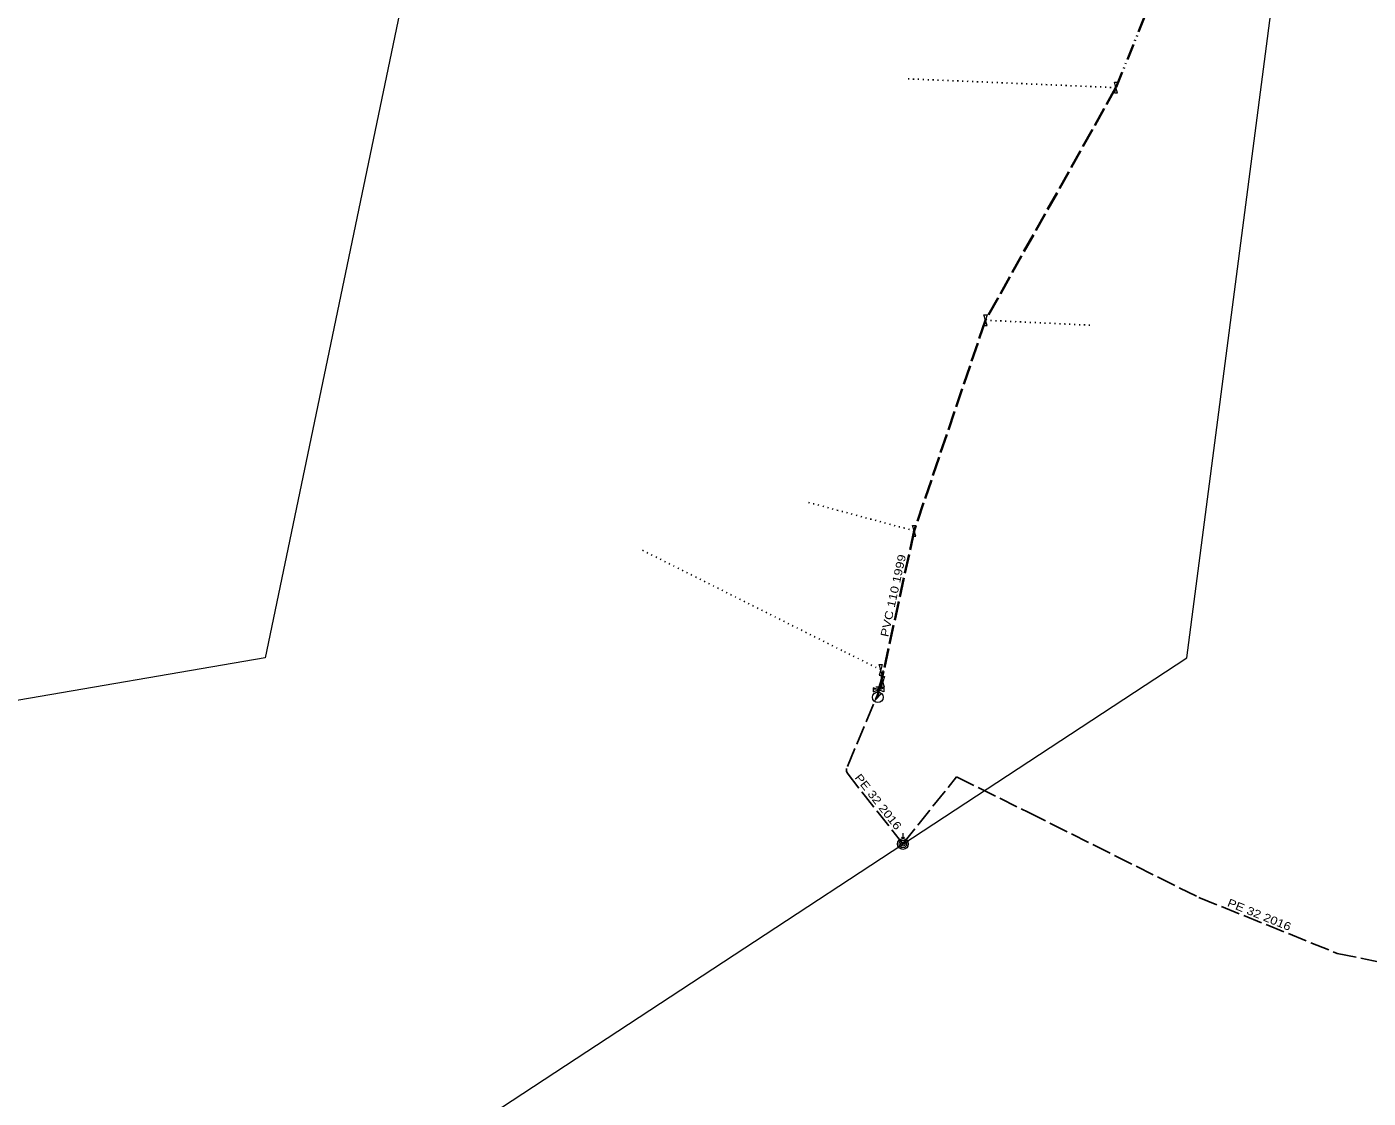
# Model space of a CAD drawing. Extents: x -582626 to -580899, y -1097611 to -1096610.
# Drawn here: x -581490.3 to -581365.1, y -1097012.4 to -1096912.4 of the extents above; entities that cross this region are included whole.
import ezdxf
from ezdxf.enums import TextEntityAlignment as Align

# ---------------------------------------------------------------- set-up
doc = ezdxf.new("R2010")
doc.units = 0
doc.header["$LTSCALE"] = 0.3
for name, pattern in [('DASH_DOUBLE_DOT', [9.2, 5, -1.2, 0.3, -1.2, 0.3, -1.2]), ('DOTTED', [1.5, 0.3, -1.2]), ('LONG_DASHED', [7.5, 6, -1.5])]:
    doc.linetypes.add(name, pattern=pattern)
for name, color, linetype, lineweight in [('1', 7, 'Continuous', 13), ('10', 7, 'Continuous', 13), ('35', 7, 'LONG_DASHED', 35), ('36', 7, 'DASH_DOUBLE_DOT', 35), ('50', 7, 'LONG_DASHED', 25), ('51', 7, 'DOTTED', 25)]:
    doc.layers.add(name, color=color, linetype=linetype, lineweight=lineweight)
doc.layers.add('16', color=7, linetype='Continuous')
doc.layers.add('19', color=7, linetype='Continuous')

msp = doc.modelspace()

# ---------------------------------------------------------------- linework, layer by layer
at = {"layer": '1'}
msp.add_lwpolyline([(-582625.57, -1097394.66), (-582612.34, -1097467.421), (-582321.299, -1097262.369), (-581897.965, -1097202.837), (-581719.372, -1097182.994), (-581593.695, -1097110.233), (-581382.028, -1096971.327), (-581362.184, -1096819.192), (-581322.497, -1096739.817), (-581210.049, -1096733.202), (-581097.601, -1096686.9), (-580905.778, -1096719.973), (-580899.163, -1096627.369), (-581084.372, -1096614.14), (-581216.663, -1096680.285), (-581368.799, -1096686.9), (-581434.945, -1096812.577), (-581468.018, -1096971.327), (-581659.84, -1097004.4), (-581831.82, -1097110.233), (-582314.684, -1097169.765), (-582519.736, -1097295.442), (-582625.57, -1097394.66)], close=True, dxfattribs=at)
at = {"layer": '10'}
for p, q in [((-581411.204, -1096975.373), (-581410.497, -1096974.666)), ((-581411.2, -1096974.219), (-581410.5, -1096974.219)), ((-581410.793, -1096974.069), (-581411.043, -1096974.069)), ((-581410.85, -1096974.519), (-581410.85, -1096974.219)), ((-581408.516, -1096988.209), (-581408.657, -1096988.068))]:
    msp.add_line(p, q, dxfattribs=at)
for points in [[(-581388.633, -1096918.118), (-581388.783, -1096917.618), (-581388.483, -1096917.618), (-581388.633, -1096918.118), (-581388.783, -1096918.618), (-581388.483, -1096918.618)], [(-581400.808, -1096939.828), (-581400.958, -1096939.328), (-581400.658, -1096939.328), (-581400.808, -1096939.828), (-581400.958, -1096940.328), (-581400.658, -1096940.328)], [(-581407.46, -1096959.484), (-581407.61, -1096958.984), (-581407.31, -1096958.984), (-581407.46, -1096959.484), (-581407.61, -1096959.984), (-581407.31, -1096959.984)], [(-581410.585, -1096972.45), (-581410.735, -1096971.95), (-581410.435, -1096971.95), (-581410.585, -1096972.45), (-581410.735, -1096972.95), (-581410.435, -1096972.95)], [(-581410.392, -1096973.578), (-581410.542, -1096973.078), (-581410.242, -1096973.078), (-581410.392, -1096973.578), (-581410.542, -1096974.078), (-581410.242, -1096974.078)]]:
    msp.add_lwpolyline(points, close=True, dxfattribs=at)
for points in [[(-581410.793, -1096974.319), (-581410.293, -1096974.132), (-581410.293, -1096974.506), (-581410.793, -1096974.319), (-581411.293, -1096974.132), (-581411.293, -1096974.506), (-581410.793, -1096974.319), (-581410.793, -1096974.069), (-581410.543, -1096974.069)], [(-581408.516, -1096987.709), (-581408.516, -1096988.209), (-581408.375, -1096988.068)]]:
    msp.add_lwpolyline(points, dxfattribs=at)
for centre, radius in [((-581410.8498, -1096975.0187), 0.5), ((-581408.5133, -1096988.7115), 0.5), ((-581408.5133, -1096988.7115), 0.35), ((-581408.5133, -1096988.7115), 0.2)]:
    msp.add_circle(centre, radius, dxfattribs=at)
at = {"layer": '35'}
msp.add_lwpolyline([(-581388.633, -1096918.118), (-581400.808, -1096939.828), (-581407.46, -1096959.484), (-581410.318, -1096972.582), (-581410.528, -1096973.542), (-581410.793, -1096974.319), (-581410.85, -1096975.019)], dxfattribs=at)
at = {"layer": '36'}
msp.add_lwpolyline([(-581370.994, -1096843.984), (-581373.727, -1096866.006), (-581377.691, -1096885.792), (-581384.916, -1096908.945), (-581388.633, -1096918.118)], dxfattribs=at)
at = {"layer": '50'}
msp.add_lwpolyline([(-581410.392, -1096973.578), (-581413.767, -1096981.681), (-581413.782, -1096981.904), (-581413.73, -1096982.081), (-581408.514, -1096988.711), (-581403.522, -1096982.454), (-581396.825, -1096985.755), (-581380.89, -1096993.711), (-581367.988, -1096998.918), (-581338.24, -1097005.156), (-581327.828, -1097004.957), (-581321.866, -1097006.642), (-581321.47, -1097007.123), (-581319.049, -1097010.467)], dxfattribs=at)
at = {"layer": '51'}
for p, q in [((-581388.633, -1096918.118), (-581408.301, -1096917.289)), ((-581400.808, -1096939.828), (-581391.052, -1096940.295)), ((-581407.46, -1096959.484), (-581417.4, -1096956.813))]:
    msp.add_line(p, q, dxfattribs=at)
at = {"layer": '51', "linetype": 'DASH_DOUBLE_DOT'}
msp.add_line((-581410.392, -1096973.578), (-581410.528, -1096973.542), dxfattribs=at)
at = {"layer": '51'}
msp.add_lwpolyline([(-581410.318, -1096972.582), (-581410.585, -1096972.45), (-581414.224, -1096970.643), (-581432.906, -1096961.254)], dxfattribs=at)

# ---------------------------------------------------------------- texts
at = {"layer": '16', "width": 1.2}
msp.add_text('PVC 110 1999', height=0.75, rotation=77.691, dxfattribs=at).set_placement((-581409.0525, -1096965.6104), align=Align.CENTER)
at = {"layer": '19', "width": 1.2}
for rotation, p in [(308.193, (-581411.1122, -1096985.0031)), (338.022, (-581375.3983, -1096995.6578))]:
    msp.add_text('PE 32 2016', height=0.75, rotation=rotation, dxfattribs=at).set_placement(p, align=Align.CENTER)

doc.saveas('drawing.dxf')
